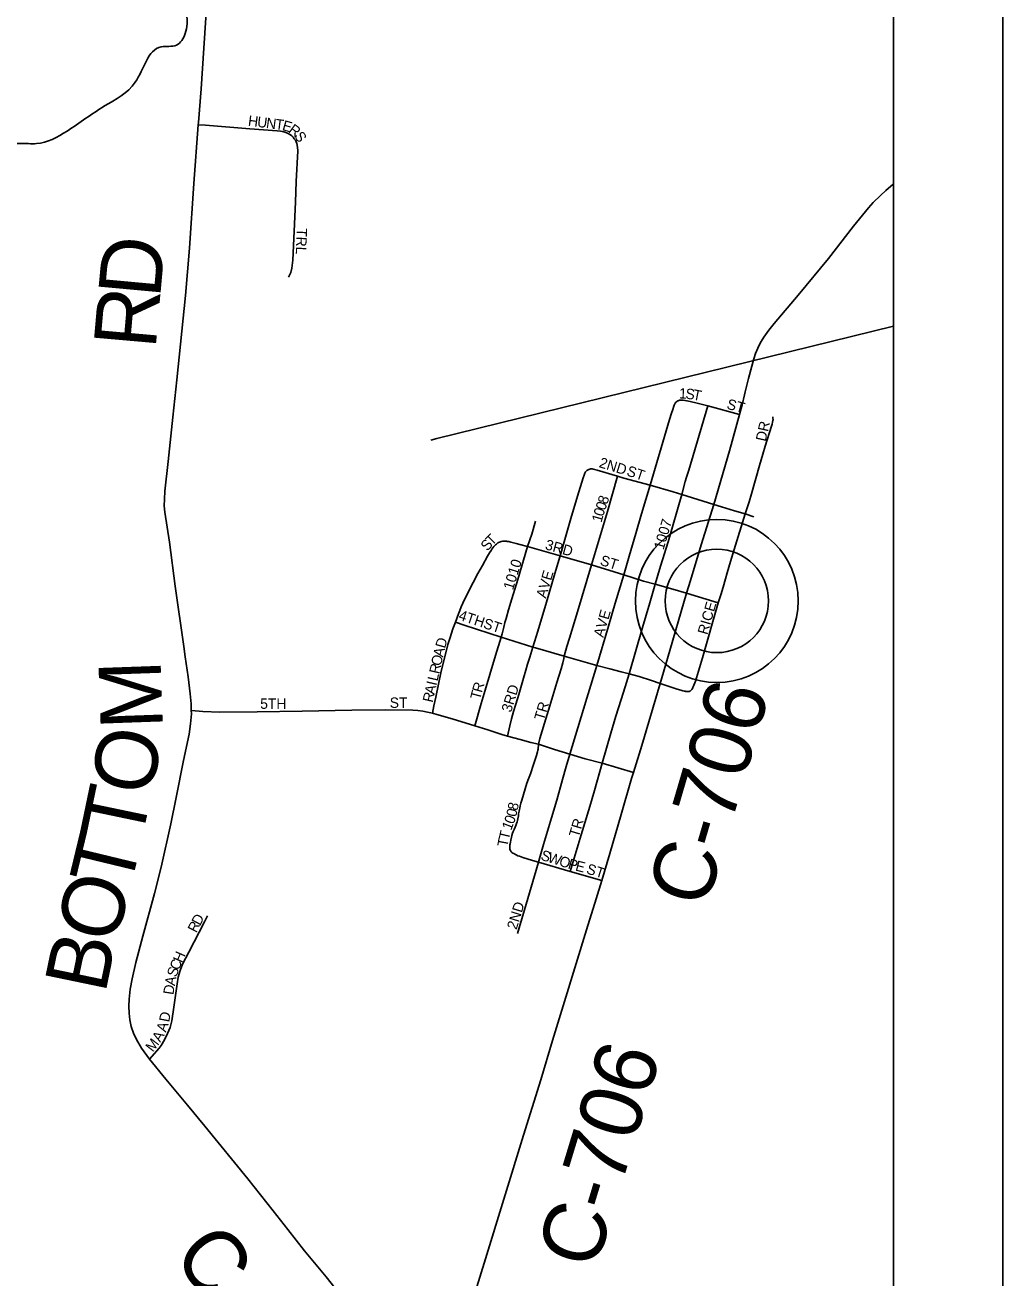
# Model space of a CAD drawing. Extents: x 0 to 34, y 0 to 22.
# Drawn here: x 30.024 to 30.917, y 15.873 to 17.017 of the extents above; entities that cross this region are included whole.
import ezdxf

# ---------------------------------------------------------------- set-up
doc = ezdxf.new("R2010")
doc.units = 0
for name, color, linetype in [('GM_X_Adjacent_County', 7, 'Continuous'), ('GM_X_County', 7, 'Continuous'), ('GM_X_County_Road', 7, 'Continuous'), ('GM_X_County_Road_Text', 7, 'Continuous'), ('GM_X_Minor_River', 7, 'Continuous'), ('GM_X_Rail_Line', 7, 'Continuous'), ('GM_X_Township', 7, 'Continuous'), ('GM_X_Township_Subdivision', 7, 'Continuous'), ('GM_X_Township_Subdivision_Text', 7, 'Continuous'), ('GM_X_Unincorporated', 7, 'Continuous'), ('GM_X_Unincorporated_Location', 7, 'Continuous'), ('SH_Data', 7, 'Continuous')]:
    doc.layers.add(name, color=color, linetype=linetype)

msp = doc.modelspace()

# ---------------------------------------------------------------- linework, layer by layer
at = {"layer": 'GM_X_Adjacent_County'}
msp.add_lwpolyline([(24.0167, 18.0693), (24.0167, 14.1), (30.8167, 14.1), (30.8167, 17.8174)], dxfattribs=at)
at = {"layer": 'GM_X_County'}
msp.add_lwpolyline([(24.0167, 18.0693), (24.0167, 14.1), (30.8167, 14.1), (30.8167, 17.8174)], dxfattribs=at)
at = {"layer": 'GM_X_County_Road'}
for points in [[(30.1819, 16.9257), (30.1821, 16.9277), (30.1846, 16.9586), (30.1896, 17.0372), (30.19, 17.0422)], [(30.1755, 16.3909), (30.1754, 16.397), (30.1746, 16.4062), (30.1725, 16.4215), (30.1698, 16.44), (30.1686, 16.4492), (30.1609, 16.5045), (30.1555, 16.5445), (30.1513, 16.5721), (30.1508, 16.5776), (30.151, 16.5839), (30.1513, 16.5911), (30.1544, 16.6181), (30.1587, 16.6586), (30.1623, 16.6927), (30.1701, 16.7698), (30.1737, 16.8131), (30.1779, 16.872), (30.1819, 16.9257)], [(30.676, 16.6611), (30.6785, 16.6701), (30.6806, 16.6792), (30.6812, 16.6818), (30.6843, 16.6941), (30.6873, 16.7054), (30.6892, 16.712), (30.6908, 16.7167), (30.6928, 16.7218), (30.6943, 16.725), (30.6959, 16.7277), (30.6983, 16.7317), (30.7029, 16.738), (30.7077, 16.7442), (30.7298, 16.7702), (30.7575, 16.8035), (30.7801, 16.8331), (30.7939, 16.8499), (30.7983, 16.8548), (30.8047, 16.8611), (30.8097, 16.8656), (30.8164, 16.8714), (30.8167, 16.8715)], [(30.6527, 16.579), (30.667, 16.628), (30.676, 16.6611)], [(30.6278, 16.4979), (30.6313, 16.5096), (30.641, 16.5422), (30.6527, 16.579)], [(30.6037, 16.4156), (30.6102, 16.4385), (30.6278, 16.4979)], [(30.5793, 16.3344), (30.5869, 16.359), (30.6037, 16.4156)], [(30.1374, 16.0727), (30.1301, 16.0825), (30.1254, 16.0906), (30.1227, 16.0963), (30.1206, 16.1023), (30.1193, 16.1084), (30.1186, 16.1147), (30.1184, 16.121), (30.1186, 16.1272), (30.1197, 16.1366), (30.1214, 16.1458), (30.1249, 16.1609), (30.1313, 16.1849), (30.142, 16.2239), (30.148, 16.2479), (30.1568, 16.2873), (30.1618, 16.3116), (30.1684, 16.3451), (30.1734, 16.3694), (30.1749, 16.3786), (30.1756, 16.3878), (30.1755, 16.3909)], [(30.5503, 16.2356), (30.5577, 16.2603), (30.568, 16.296), (30.5776, 16.3287), (30.5793, 16.3344)], [(30.4208, 15.8144), (30.444, 15.8902), (30.4788, 16.0033), (30.4946, 16.0538), (30.5052, 16.0896), (30.5164, 16.1252), (30.5364, 16.1906), (30.5453, 16.2189), (30.5503, 16.2356)], [(30.3198, 15.8469), (30.2987, 15.8737), (30.2789, 15.8976), (30.2635, 15.9171), (30.2501, 15.9341), (30.2271, 15.9633), (30.1877, 16.0113), (30.172, 16.0306), (30.1521, 16.0543), (30.1374, 16.0727)]]:
    msp.add_lwpolyline(points, dxfattribs=at)
at = {"layer": 'GM_X_Minor_River'}
msp.add_spline([(29.8147, 15.9312), (29.8117, 15.9558), (29.7953, 15.9967), (29.7918, 16.0206), (29.7756, 16.0805), (29.7599, 16.1172), (29.7507, 16.154), (29.7354, 16.1926), (29.7112, 16.1945), (29.6991, 16.1906), (29.6835, 16.1917), (29.6733, 16.1981), (29.6402, 16.2337), (29.6394, 16.2473), (29.6397, 16.2621), (29.6471, 16.2929), (29.6459, 16.3122), (29.6536, 16.3688), (29.6717, 16.3988), (29.7128, 16.432), (29.7245, 16.4426), (29.7448, 16.467), (29.7462, 16.492), (29.8196, 16.5139), (29.8122, 16.5556), (29.8085, 16.6246), (29.8106, 16.7498), (29.8172, 16.7988), (29.8262, 16.8208), (29.8348, 16.8338), (29.8458, 16.8433), (29.864, 16.8433), (29.8745, 16.8479), (29.8847, 16.8719), (29.8979, 16.8746), (29.9233, 16.8728), (29.9258, 16.8872), (29.933, 16.8993), (29.9633, 16.8991), (30.0196, 16.9087), (30.034, 16.9084), (30.062, 16.9199), (30.0963, 16.9428), (30.1243, 16.9645), (30.148, 16.9968), (30.162, 16.9984), (30.1699, 17.009), (30.1637, 17.0409), (30.1477, 17.048), (30.1042, 17.0403), (30.091, 17.0414), (29.9739, 17.0592), (29.9391, 17.061), (29.9137, 17.067), (29.9042, 17.0688), (29.8769, 17.0866), (29.892, 17.0965), (29.917, 17.0954), (29.9355, 17.1179), (29.9506, 17.1244), (29.9611, 17.1331), (29.989, 17.1753), (30.0127, 17.1986), (30.0286, 17.2036), (30.0706, 17.2094), (30.1631, 17.2583), (30.2284, 17.3082), (30.2462, 17.3162), (30.2567, 17.3178)], degree=3, dxfattribs=at)
at = {"layer": 'GM_X_Rail_Line'}
for points in [[(30.3996, 16.6392), (30.8167, 16.7418)], [(30.3941, 16.6378), (30.3996, 16.6392)]]:
    msp.add_lwpolyline(points, dxfattribs=at)
at = {"layer": 'GM_X_Township'}
msp.add_line((30.8167, 15.629), (30.8167, 17.8174), dxfattribs=at)
at = {"layer": 'GM_X_Township_Subdivision'}
for points in [[(30.1819, 16.9257), (30.1884, 16.9252), (30.2289, 16.922), (30.2538, 16.9201), (30.257, 16.9197), (30.2601, 16.9191), (30.2632, 16.918), (30.266, 16.9164), (30.2672, 16.9155), (30.2685, 16.9142), (30.2694, 16.9129), (30.2705, 16.9115), (30.2712, 16.91), (30.2718, 16.9084), (30.2725, 16.9052), (30.2727, 16.902), (30.2714, 16.8738), (30.2706, 16.8551), (30.2681, 16.8021), (30.2673, 16.7946), (30.2664, 16.7909), (30.2643, 16.7864)], [(30.5944, 16.5965), (30.6122, 16.6565), (30.6141, 16.6624), (30.6151, 16.6657), (30.6161, 16.6686), (30.6165, 16.6696), (30.6168, 16.6704), (30.6171, 16.671), (30.6174, 16.6714), (30.6177, 16.6719), (30.6181, 16.6723), (30.6185, 16.6726), (30.619, 16.6731), (30.6197, 16.6735)], [(30.6197, 16.6735), (30.6202, 16.6737), (30.6208, 16.674), (30.6212, 16.6741), (30.6218, 16.6741), (30.6223, 16.6742), (30.623, 16.6742), (30.6237, 16.6742), (30.6248, 16.6741), (30.6263, 16.674), (30.6281, 16.6737), (30.6309, 16.6731), (30.6374, 16.6715), (30.6446, 16.6696), (30.6471, 16.6689)], [(30.6233, 16.5881), (30.6266, 16.6), (30.6277, 16.6038), (30.6297, 16.6104), (30.6471, 16.6689)], [(30.6471, 16.6689), (30.676, 16.6611)], [(30.6812, 16.5703), (30.6848, 16.5815), (30.6869, 16.5886), (30.6944, 16.6145), (30.6975, 16.6249), (30.6996, 16.6322), (30.7054, 16.6506), (30.706, 16.6524), (30.7063, 16.6541), (30.7065, 16.6556), (30.7067, 16.6567), (30.7066, 16.6579), (30.7064, 16.659)], [(30.5123, 16.5322), (30.522, 16.5663), (30.5281, 16.5866), (30.5333, 16.6033), (30.5341, 16.6057), (30.5346, 16.6068), (30.535, 16.6076), (30.5352, 16.6081), (30.5355, 16.6087), (30.5358, 16.609), (30.5362, 16.6095), (30.5366, 16.6099), (30.5372, 16.6103), (30.5379, 16.6107), (30.5386, 16.611)], [(30.5386, 16.611), (30.5394, 16.6112), (30.5401, 16.6114), (30.5408, 16.6114), (30.5415, 16.6114), (30.5426, 16.6112), (30.5437, 16.611), (30.546, 16.6103), (30.5647, 16.6048)], [(30.5408, 16.524), (30.5554, 16.5727), (30.5647, 16.6048)], [(30.5647, 16.6048), (30.5705, 16.6031), (30.5944, 16.5965)], [(30.5704, 16.5148), (30.5752, 16.5318), (30.5815, 16.5526), (30.5867, 16.5704), (30.5944, 16.5965)], [(30.5944, 16.5965), (30.6154, 16.5906), (30.6233, 16.5881)], [(30.5991, 16.5061), (30.604, 16.5227), (30.6108, 16.545), (30.6233, 16.5881)], [(30.6233, 16.5881), (30.6332, 16.5852), (30.6527, 16.579)], [(30.6527, 16.579), (30.6597, 16.5767), (30.6715, 16.5731), (30.6812, 16.5703)], [(30.4825, 16.5405), (30.4864, 16.5519), (30.4899, 16.5636)], [(30.6566, 16.4892), (30.659, 16.4964), (30.6612, 16.5035), (30.6633, 16.5111), (30.6647, 16.5165), (30.6679, 16.5269), (30.6713, 16.5379), (30.6812, 16.5703)], [(30.6812, 16.5703), (30.6892, 16.5677)], [(30.4166, 16.4715), (30.4194, 16.479), (30.4207, 16.4823), (30.422, 16.4856), (30.4235, 16.4888), (30.4251, 16.4923), (30.4267, 16.4956), (30.4287, 16.4995), (30.4372, 16.516), (30.4413, 16.5234), (30.4461, 16.5317), (30.4479, 16.5349), (30.4492, 16.537), (30.45, 16.5382), (30.4508, 16.5394), (30.4518, 16.5406), (30.4523, 16.5412), (30.4533, 16.5421), (30.4542, 16.5429), (30.4548, 16.5434), (30.4555, 16.5439), (30.4561, 16.5442), (30.4568, 16.5446), (30.4578, 16.545)], [(30.4578, 16.545), (30.4586, 16.5452), (30.4596, 16.5454), (30.4603, 16.5456), (30.4611, 16.5456), (30.4623, 16.5456), (30.4632, 16.5454), (30.464, 16.5453), (30.4653, 16.5451), (30.4672, 16.5446), (30.4721, 16.5434), (30.4755, 16.5424), (30.4825, 16.5405)], [(30.4586, 16.4578), (30.4594, 16.461), (30.4603, 16.4646), (30.4608, 16.4671), (30.4619, 16.4712), (30.463, 16.475), (30.4652, 16.4829), (30.4681, 16.4928), (30.4737, 16.5104), (30.4825, 16.5405)], [(30.4825, 16.5405), (30.493, 16.5376), (30.5123, 16.5322)], [(30.4875, 16.4488), (30.4919, 16.4634), (30.4997, 16.4899), (30.5074, 16.5161), (30.5123, 16.5322)], [(30.5123, 16.5322), (30.5408, 16.524)], [(30.5161, 16.4405), (30.5185, 16.4493), (30.5208, 16.4568), (30.5283, 16.4811), (30.5408, 16.524)], [(30.5408, 16.524), (30.5617, 16.5175), (30.5704, 16.5148)], [(30.5459, 16.4321), (30.5564, 16.4678), (30.5627, 16.4889), (30.5704, 16.5148)], [(30.5704, 16.5148), (30.5883, 16.5091), (30.5991, 16.5061)], [(30.5752, 16.4244), (30.5876, 16.4666), (30.5942, 16.4893), (30.5991, 16.5061)], [(30.5991, 16.5061), (30.6153, 16.5017), (30.6278, 16.4979)], [(30.6278, 16.4979), (30.6566, 16.4892)], [(30.6037, 16.4156), (30.612, 16.4129), (30.6155, 16.4117), (30.6193, 16.4105), (30.6225, 16.4095), (30.6244, 16.4089), (30.6256, 16.4086), (30.6265, 16.4084), (30.6272, 16.4082), (30.6277, 16.4082), (30.6284, 16.4081), (30.6288, 16.4081), (30.6292, 16.4081), (30.6296, 16.4082), (30.6301, 16.4083), (30.6306, 16.4084), (30.6309, 16.4086), (30.6313, 16.4088), (30.6317, 16.4091), (30.632, 16.4094), (30.6323, 16.4097), (30.6327, 16.4102), (30.633, 16.4107), (30.6331, 16.411), (30.6335, 16.4118), (30.6339, 16.4126), (30.6344, 16.4139), (30.6352, 16.4161), (30.6358, 16.4178), (30.6423, 16.4391), (30.6566, 16.4892)], [(30.3958, 16.3884), (30.397, 16.395), (30.3987, 16.4032), (30.4038, 16.4267), (30.4082, 16.4447), (30.4098, 16.451), (30.4106, 16.4539), (30.4118, 16.4575), (30.4144, 16.4655), (30.4166, 16.4715)], [(30.4166, 16.4715), (30.4246, 16.4689), (30.4586, 16.4578)], [(30.4343, 16.3769), (30.4401, 16.3974), (30.4438, 16.4096), (30.4481, 16.4239), (30.4534, 16.4412), (30.4586, 16.4578)], [(30.4586, 16.4578), (30.4875, 16.4488)], [(30.4641, 16.3675), (30.4664, 16.377), (30.4679, 16.3832), (30.4698, 16.3899), (30.4718, 16.3967), (30.4745, 16.4055), (30.477, 16.4141), (30.4789, 16.4205), (30.481, 16.4276), (30.4826, 16.4333), (30.4846, 16.4396), (30.4875, 16.4488)], [(30.4875, 16.4488), (30.4897, 16.448), (30.5161, 16.4405)], [(30.4925, 16.36), (30.4937, 16.3653), (30.4981, 16.3792), (30.503, 16.3951), (30.5094, 16.4164), (30.5131, 16.429), (30.5147, 16.4345), (30.5157, 16.4385), (30.5161, 16.4405)], [(30.5161, 16.4405), (30.5459, 16.4321)], [(30.5213, 16.351), (30.5234, 16.358), (30.5368, 16.4023), (30.5404, 16.414), (30.5459, 16.4321)], [(30.5459, 16.4321), (30.5576, 16.4289), (30.568, 16.4262), (30.5752, 16.4244)], [(30.5506, 16.3428), (30.5585, 16.3701), (30.5631, 16.3858), (30.568, 16.401), (30.5716, 16.4125), (30.5752, 16.4244)], [(30.5752, 16.4244), (30.5845, 16.4218), (30.5956, 16.4184), (30.6037, 16.4156)], [(30.1755, 16.3909), (30.1828, 16.3902), (30.1859, 16.3899), (30.2014, 16.3893), (30.2355, 16.3898), (30.2767, 16.3903), (30.3222, 16.3911), (30.3532, 16.3915), (30.3778, 16.3913), (30.3824, 16.3909), (30.3869, 16.3903), (30.3911, 16.3895), (30.3958, 16.3884)], [(30.3958, 16.3884), (30.3997, 16.3872), (30.4137, 16.3832), (30.4343, 16.3769)], [(30.4343, 16.3769), (30.4462, 16.3731), (30.4591, 16.369), (30.4641, 16.3675)], [(30.4641, 16.3675), (30.4757, 16.3643), (30.4855, 16.3617), (30.4925, 16.36)], [(30.4924, 16.2525), (30.4872, 16.2539), (30.4782, 16.2567), (30.4751, 16.2578), (30.4737, 16.2583), (30.4723, 16.259), (30.4708, 16.2597), (30.47, 16.2602), (30.4691, 16.2607), (30.4683, 16.2613), (30.4677, 16.2618), (30.4672, 16.2624), (30.4669, 16.263), (30.4667, 16.2635), (30.4664, 16.2642), (30.4664, 16.2647), (30.4663, 16.2654), (30.4663, 16.2661), (30.4663, 16.2672), (30.4664, 16.2682), (30.4666, 16.2693), (30.4669, 16.2707), (30.4672, 16.2725), (30.4678, 16.2751), (30.4683, 16.2767), (30.4689, 16.2789), (30.4694, 16.2804), (30.4702, 16.2821), (30.4712, 16.2845), (30.4718, 16.2859), (30.4724, 16.2876), (30.473, 16.2892), (30.4734, 16.2904), (30.4737, 16.2921), (30.4742, 16.2947), (30.4744, 16.2964), (30.4748, 16.299), (30.4751, 16.3005), (30.4754, 16.3018), (30.4758, 16.3037), (30.4765, 16.3062), (30.4774, 16.309), (30.4789, 16.3142), (30.4804, 16.3193), (30.482, 16.3245), (30.4834, 16.3285), (30.4851, 16.3332), (30.4881, 16.3415), (30.4899, 16.347), (30.4907, 16.3498), (30.4916, 16.353), (30.492, 16.3548), (30.4922, 16.3557), (30.4923, 16.3572), (30.4924, 16.3586), (30.4925, 16.36)], [(30.4925, 16.36), (30.5073, 16.3553), (30.5213, 16.351)], [(30.4924, 16.2525), (30.4927, 16.2536), (30.497, 16.2685), (30.5045, 16.293), (30.5092, 16.309), (30.5145, 16.3278), (30.5179, 16.3398), (30.5213, 16.351)], [(30.5213, 16.351), (30.5353, 16.3469), (30.5506, 16.3428)], [(30.5214, 16.244), (30.5316, 16.2773), (30.5395, 16.3032), (30.5438, 16.3177), (30.5506, 16.3428)], [(30.5506, 16.3428), (30.5793, 16.3344)], [(30.4735, 16.1872), (30.4813, 16.214), (30.4888, 16.24), (30.4924, 16.2525)], [(30.4924, 16.2525), (30.5214, 16.244)], [(30.5214, 16.244), (30.5503, 16.2356)], [(30.1374, 16.0727), (30.1461, 16.0825), (30.1479, 16.085), (30.1511, 16.0903), (30.1538, 16.0959), (30.1561, 16.1016), (30.1576, 16.1076), (30.1594, 16.1199), (30.1625, 16.1414), (30.1636, 16.1475), (30.1652, 16.1535), (30.1674, 16.1593), (30.1731, 16.1703), (30.1875, 16.1978), (30.1904, 16.2033)]]:
    msp.add_lwpolyline(points, dxfattribs=at)
at = {"layer": 'GM_X_Unincorporated'}
for radius in [0.0744, 0.0472]:
    msp.add_circle((30.6554, 16.4909), radius, dxfattribs=at)
at = {"layer": 'GM_X_Unincorporated_Location'}
msp.add_line((30.6554, 16.4909), (30.6554, 16.4909), dxfattribs=at)
at = {"layer": 'SH_Data'}
for points in [[(23.9167, 21), (30.9167, 21), (30.9167, 14), (23.9167, 14)], [(24.0167, 20.9), (30.8167, 20.9), (30.8167, 14.1), (24.0167, 14.1)]]:
    msp.add_lwpolyline(points, close=True, dxfattribs=at)

# ---------------------------------------------------------------- texts
at = {"layer": 'GM_X_County_Road_Text'}
for s, height, rotation, p in [('D', 0.0568, 84.7653, (30.1469, 16.7665)), ('R', 0.0568, 84.9861, (30.1428, 16.7201)), ('M', 0.0568, 92.0309, (30.1496, 16.3747)), ('C-706', 0.05682, 73.6407, (30.6457, 16.2089)), ('O', 0.0568, 78.4792, (30.1384, 16.3111)), ('T', 0.0568, 78.2261, (30.1297, 16.2692)), ('T', 0.0568, 76.4401, (30.1193, 16.226)), ('O', 0.0568, 75.1279, (30.1061, 16.1763)), ('B', 0.0568, 78.2874, (30.0968, 16.1314)), ('C-706', 0.05682, 73.1209, (30.5446, 15.8788)), ('C-57', 0.05682, 308.7654, (30.157, 15.8925))]:
    msp.add_text(s, height=height, rotation=rotation, dxfattribs=at).set_placement(p)
at = {"layer": 'GM_X_Township_Subdivision_Text'}
for s, rotation, p in [('H', 352.5469, (30.2269, 16.9249)), ('U', 352.5639, (30.2352, 16.9238)), ('N', 352.5469, (30.2434, 16.9228)), ('T', 352.5462, (30.2517, 16.9217)), ('E', 343.9758, (30.2579, 16.9209)), ('R', 323.8101, (30.2636, 16.9194)), ('S', 303.7583, (30.269, 16.9156)), ('TRL', 267.7987, (30.2718, 16.8314)), ('1', 358.0014, (30.6208, 16.6758)), ('S', 353.6749, (30.6264, 16.6756)), ('T', 348.9473, (30.6329, 16.6749)), ('ST', 345.0622, (30.6638, 16.6665)), ('DR', 77.4789, (30.7, 16.636)), ('2ND', 342.8967, (30.5472, 16.6132)), ('ST', 341.5607, (30.5723, 16.6057)), ('8', 70.4491, (30.5551, 16.5785)), ('0', 73.3725, (30.5516, 16.5675)), ('0', 71.407, (30.5533, 16.573)), ('1', 73.9645, (30.55, 16.562)), ('1007', 73.4896, (30.6067, 16.537)), ('T', 44.9807, (30.4501, 16.5408)), ('S', 50.8452, (30.4461, 16.5359)), ('3RD', 344.3587, (30.498, 16.5382)), ('1010', 72.8967, (30.4692, 16.5003)), ('ST', 342.6538, (30.5481, 16.524)), ('AVE', 73.497, (30.4992, 16.4928)), ('AVE', 74.0556, (30.5517, 16.457)), ('RICE', 73.8072, (30.6467, 16.4595)), ('4TH', 341.5651, (30.4189, 16.474)), ('ST', 341.5782, (30.4414, 16.4665)), ('D', 74.1927, (30.4072, 16.4471)), ('O', 77.101, (30.4034, 16.431)), ('A', 76.5893, (30.4053, 16.4391)), ('R', 77.0986, (30.4018, 16.4237)), ('I', 77.098, (30.3993, 16.4131)), ('L', 77.1037, (30.4003, 16.4172)), ('R', 73.9078, (30.4408, 16.4066)), ('R', 77.1182, (30.3958, 16.3977)), ('A', 77.1037, (30.3975, 16.405)), ('T', 75.5596, (30.4392, 16.4002)), ('3RD', 72.9014, (30.4675, 16.3886)), ('5TH', 0, (30.2384, 16.3924)), ('ST', 0, (30.3567, 16.3933)), ('TR', 73.6174, (30.4975, 16.3811)), ('0', 77.3361, (30.4721, 16.2933)), ('8', 77.312, (30.4733, 16.299)), ('0', 70.4915, (30.4698, 16.2866)), ('TR', 73.6056, (30.5292, 16.2745)), ('T', 76.7657, (30.4654, 16.2723)), ('1', 68.6509, (30.4675, 16.2809)), ('T', 79.3652, (30.4641, 16.2659)), ('S', 342.092, (30.4939, 16.2548)), ('W', 342.0986, (30.5003, 16.2528)), ('O', 342.1198, (30.5106, 16.2495)), ('P', 343.9355, (30.5188, 16.2468)), ('E', 345.8198, (30.5256, 16.2449)), ('ST', 342.6413, (30.5356, 16.2423)), ('2ND', 72.899, (30.4725, 16.1903)), ('R', 63.1634, (30.1801, 16.1873)), ('D', 61.9879, (30.1835, 16.1939)), ('C', 66.728, (30.1639, 16.153)), ('H', 66.3681, (30.1669, 16.1599)), ('S', 70.6494, (30.1618, 16.1469)), ('D', 81.2239, (30.1591, 16.1309)), ('A', 79.6717, (30.1604, 16.1391)), ('D', 79.0795, (30.1552, 16.1059)), ('A', 59.6785, (30.1471, 16.0875)), ('A', 71.7996, (30.1522, 16.0967)), ('M', 52.8678, (30.1404, 16.0785))]:
    msp.add_text(s, height=0.00947, rotation=rotation, dxfattribs=at).set_placement(p)

doc.saveas('drawing.dxf')
